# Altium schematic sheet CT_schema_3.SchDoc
size 283 x 147 mm
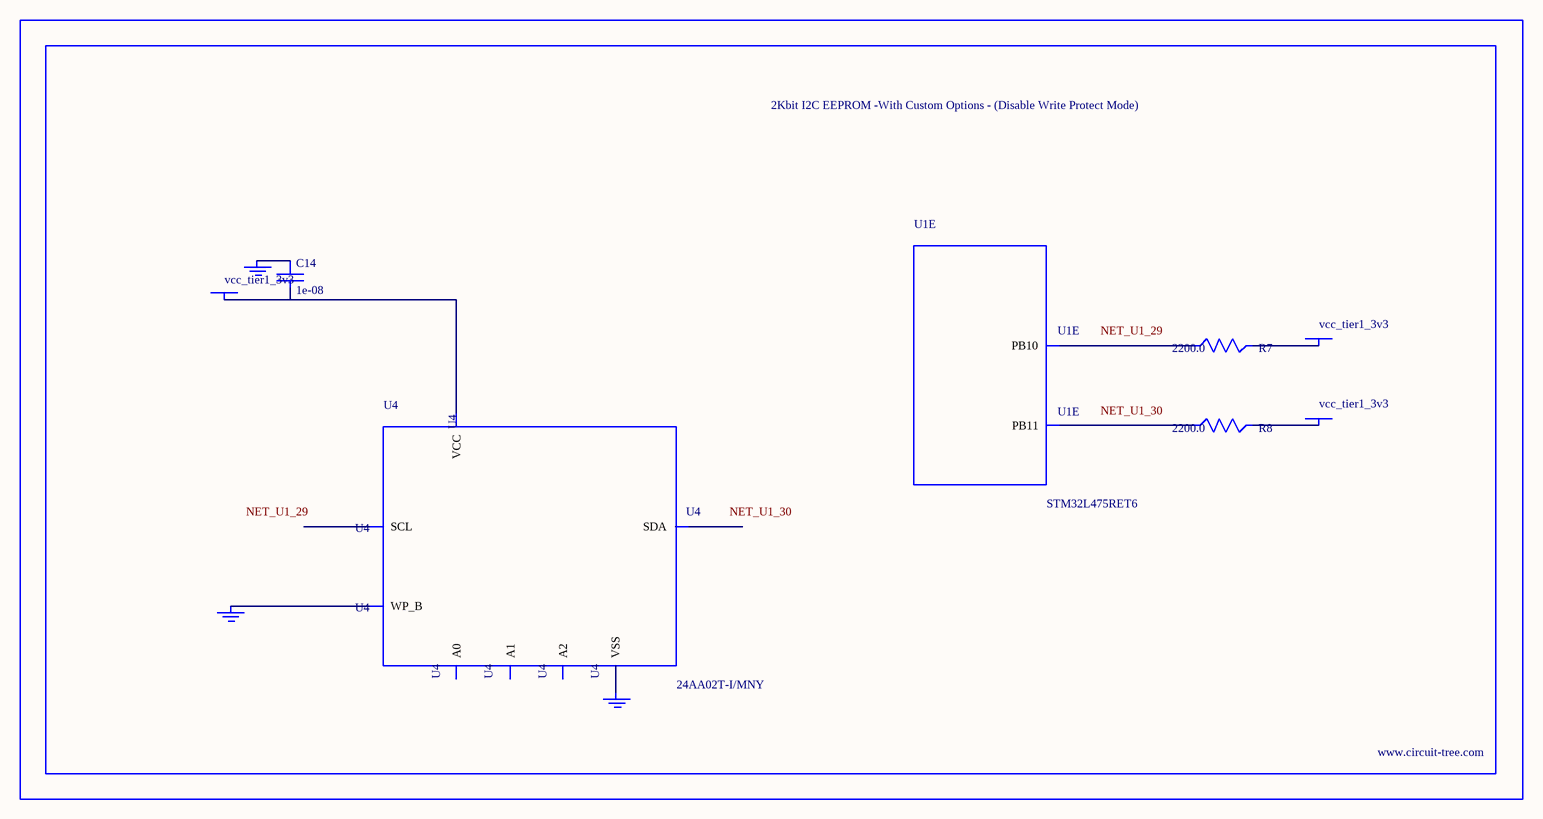
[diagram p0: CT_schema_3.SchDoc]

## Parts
BORDER2  (no value)
C14  1e-08  [C0402]
GND_INSTANCE_2_0  (no value)
GND_INSTANCE_2_1  (no value)
GND_INSTANCE_2_2  (no value)
POWER_INSTANCE_2_0  vcc_tier1_3v3
POWER_INSTANCE_2_1  vcc_tier1_3v3
POWER_INSTANCE_2_2  vcc_tier1_3v3
R7  2200.0  [R0603]
R8  2200.0  [R0603]
U1  STM32L475RET6  [LQFP64]  (part E of 8)
U4  24AA02T-I/MNY  [TDFN-8/6MM]

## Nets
NetC14_1: C14.1 GND_INSTANCE_2_1.0(GND)
NetC14_2: C14.2 POWER_INSTANCE_2_0.0(PWR) U4.8(VCC)
NetGND_INSTANCE_2_0_0: GND_INSTANCE_2_0.0(GND) U4.7(WP_B)
NetGND_INSTANCE_2_2_0: GND_INSTANCE_2_2.0(GND) U4.4(VSS)
NetPOWER_INSTANCE_2_1_0: POWER_INSTANCE_2_1.0(PWR) R7.2
NetPOWER_INSTANCE_2_2_0: POWER_INSTANCE_2_2.0(PWR) R8.2
NetR7_1: R7.1 U1.29(PB10)
NetR8_1: R8.1 U1.30(PB11)

Not connected (* = marked no-connect by the designer): U4 1(A0) 2(A1) 3(A2) 5(SDA) 6(SCL)

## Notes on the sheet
- Labels drawn without touching a wire or pin: NET_U1_29, NET_U1_30

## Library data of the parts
BORDER2 = BORDER_PAGE2
C14 = C0402C103K3RAC
GND_INSTANCE_2_0-GND_INSTANCE_2_2 = GND
POWER_INSTANCE_2_0-POWER_INSTANCE_2_2 = PWR
R7 R8 = RC0603JR-072K2L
